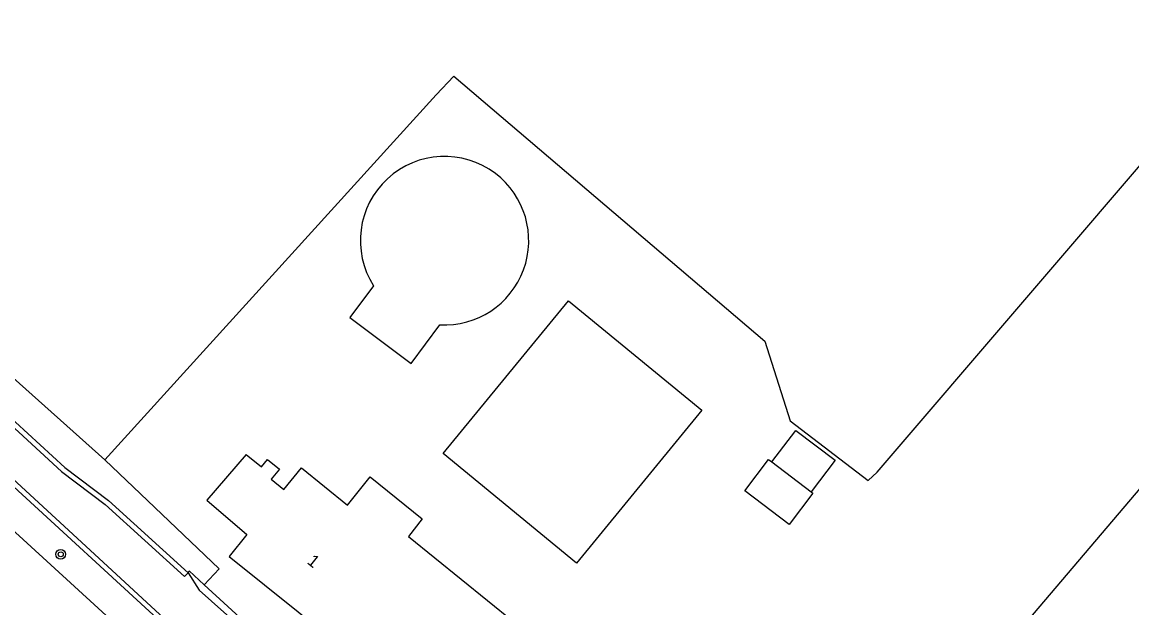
# Model space of a CAD drawing. Extents: x 124000 to 129000, y 395500 to 397503.
# Drawn here: x 126609.1 to 126699.1, y 396312 to 396359.4 of the extents above; entities that cross this region are included whole.
import ezdxf

# ---------------------------------------------------------------- set-up
doc = ezdxf.new("R2010")
doc.units = 0
for name, color, linetype in [('gg-afsc-erfafscheiding', 7, 'Continuous'), ('gg-anno-huisnummerreeks BGT', 7, 'Continuous'), ('gg-bbg-bijgebouw', 7, 'Continuous'), ('gg-bbg-gedigitaliseerde bebouwing', 7, 'Continuous'), ('gg-bbg-gedigitaliseerde bijgebouw', 7, 'Continuous'), ('gg-bbg-hoofdgebouw', 7, 'Continuous'), ('gg-bbg-luifel en loopbrug', 7, 'Continuous'), ('gg-knt-bronhoudergrens', 7, 'Continuous'), ('gg-knt-verharding', 7, 'Continuous'), ('gt-symb-boom', 7, 'Continuous'), ('gx-grn-maaiveld', 7, 'Continuous')]:
    doc.layers.add(name, color=color, linetype=linetype)

# ---------------------------------------------------------------- blocks, each defined once
blk = doc.blocks.new('gt0-BOOM')
at = {"layer": 'gt-symb-boom'}
for radius in [0.4, 0.2]:
    blk.add_circle((0, 0), radius, dxfattribs=at)

msp = doc.modelspace()

# ---------------------------------------------------------------- linework, layer by layer
at = {"layer": 'gg-afsc-erfafscheiding'}
msp.add_line((126625.076, 396315.118), (126615.812, 396323.938), dxfattribs=at)
at = {"layer": 'gg-bbg-bijgebouw'}
msp.add_lwpolyline([(126654.059, 396315.583), (126643.244, 396324.459), (126653.408, 396336.843), (126664.223, 396327.967), (126654.059, 396315.583)], dxfattribs=at)
at = {"layer": 'gg-bbg-gedigitaliseerde bebouwing'}
msp.add_line((126627.266, 396324.376), (126628.507, 396323.372), dxfattribs=at)
msp.add_lwpolyline([(126628.507, 396323.372), (126629.004, 396323.986), (126629.975, 396323.2), (126629.302, 396322.368), (126630.336, 396321.531), (126631.758, 396323.288), (126635.481, 396320.275), (126637.337, 396322.568), (126641.55, 396319.158), (126640.427, 396317.739), (126651.106, 396309.084)], dxfattribs=at)
at = {"layer": 'gg-bbg-gedigitaliseerde bijgebouw'}
msp.add_line((126669.908, 396323.776), (126673.098, 396321.362), dxfattribs=at)
for points in [[(126637.593, 396338.049), (126635.673, 396335.471), (126640.646, 396331.767), (126642.972, 396334.892)], [(126673.098, 396321.362), (126673.234, 396321.259), (126671.303, 396318.707), (126667.714, 396321.423), (126669.645, 396323.975), (126669.908, 396323.776)]]:
    msp.add_lwpolyline(points, dxfattribs=at)
for start, end in [(52.88683, 212.42259), (266.75434, 52.88689)]:
    msp.add_arc((126643.359, 396341.711), 6.83, start, end, dxfattribs=at)
at = {"layer": 'gg-bbg-hoofdgebouw'}
msp.add_lwpolyline([(126627.266, 396324.376), (126624.074, 396320.672), (126627.322, 396317.886), (126625.892, 396316.115), (126634.365, 396309.333), (126633.536, 396308.374), (126643.715, 396300.193)], dxfattribs=at)
at = {"layer": 'gg-bbg-luifel en loopbrug'}
msp.add_lwpolyline([(126669.908, 396323.776), (126671.849, 396326.339), (126675.038, 396323.926), (126673.098, 396321.362)], dxfattribs=at)
at = {"layer": 'gg-knt-bronhoudergrens'}
for p, q in [((126615.812, 396323.938), (126642.674, 396353.542)), ((126715.183, 396339.795), (126666.923, 396283.033))]:
    msp.add_line(p, q, dxfattribs=at)
for points in [[(126553.54, 396367.113), (126560.407, 396360.984), (126580.753, 396343.047), (126595.098, 396330.361), (126616.864, 396310.462)], [(126642.674, 396353.542), (126644.102, 396355.052), (126669.334, 396333.554), (126671.395, 396327.121), (126677.717, 396322.28), (126678.443, 396322.947)], [(126678.443, 396322.947), (126702.39, 396350.885), (126715.183, 396339.795)]]:
    msp.add_lwpolyline(points, dxfattribs=at)
at = {"layer": 'gg-knt-verharding'}
msp.add_line((126623.849, 396313.809), (126625.076, 396315.118), dxfattribs=at)
for points in [[(126553.887, 396376.019), (126570.288, 396361.88), (126579.566, 396353.496), (126593.537, 396340.776), (126612.568, 396323.314), (126616.106, 396320.644), (126622.564, 396314.798)], [(126554.219, 396375.149), (126561.996, 396368.52), (126570.001, 396361.623), (126593.235, 396340.526), (126612.304, 396322.999), (126615.831, 396320.332), (126622.271, 396314.491), (126622.564, 396314.798)], [(126675.399, 396265.461), (126663.883, 396274.763), (126648.11, 396287.38), (126638.301, 396295.366), (126629.884, 396302.372), (126620.401, 396310.765), (126608.092, 396322.052), (126594.052, 396335.04), (126581.024, 396346.932), (126569.581, 396357.245), (126560.411, 396365.325), (126551.363, 396373.109)], [(126675.725, 396265.823), (126648.422, 396287.668), (126638.477, 396295.707), (126630.173, 396302.643), (126620.593, 396311.109), (126594.279, 396335.342), (126581.318, 396347.192), (126569.808, 396357.565), (126560.553, 396365.727), (126552.268, 396372.847)], [(126622.564, 396314.798), (126622.651, 396314.943), (126623.849, 396313.809)], [(126622.564, 396314.798), (126623.463, 396313.391), (126628.938, 396308.484), (126663.678, 396280.201), (126667.683, 396277.03), (126672.993, 396272.751)], [(126623.849, 396313.809), (126629.31, 396308.849), (126636.296, 396303.013)]]:
    msp.add_lwpolyline(points, dxfattribs=at)
at = {"layer": 'gx-grn-maaiveld'}
msp.add_lwpolyline([(126615.812, 396323.938), (126556.54, 396376.93), (126476.318, 396443.602), (126474.646, 396445.461), (126472.226, 396449.869), (126471.902, 396452.946), (126472.605, 396457.429), (126518.93, 396524.951), (126532.591, 396543.993), (126553.728, 396571.159), (126557.156, 396572.565), (126561.287, 396571.95), (126576.58, 396563.161), (126605.05, 396546.345), (126615.074, 396541), (126620.915, 396538.052), (126628.637, 396534.75), (126640.141, 396529.469), (126650.531, 396525.86), (126661.676, 396521.838), (126662.428, 396521.522)], dxfattribs=at)

# ---------------------------------------------------------------- block references
at = {"layer": 'gt-symb-boom'}
msp.add_blockref('gt0-BOOM', (126612.229, 396316.292), dxfattribs=at)

# ---------------------------------------------------------------- texts
at = {"layer": 'gg-anno-huisnummerreeks BGT'}
msp.add_text('1', height=1, rotation=321.3, dxfattribs=at).set_placement((126632.142, 396315.596))

doc.saveas('drawing.dxf')
